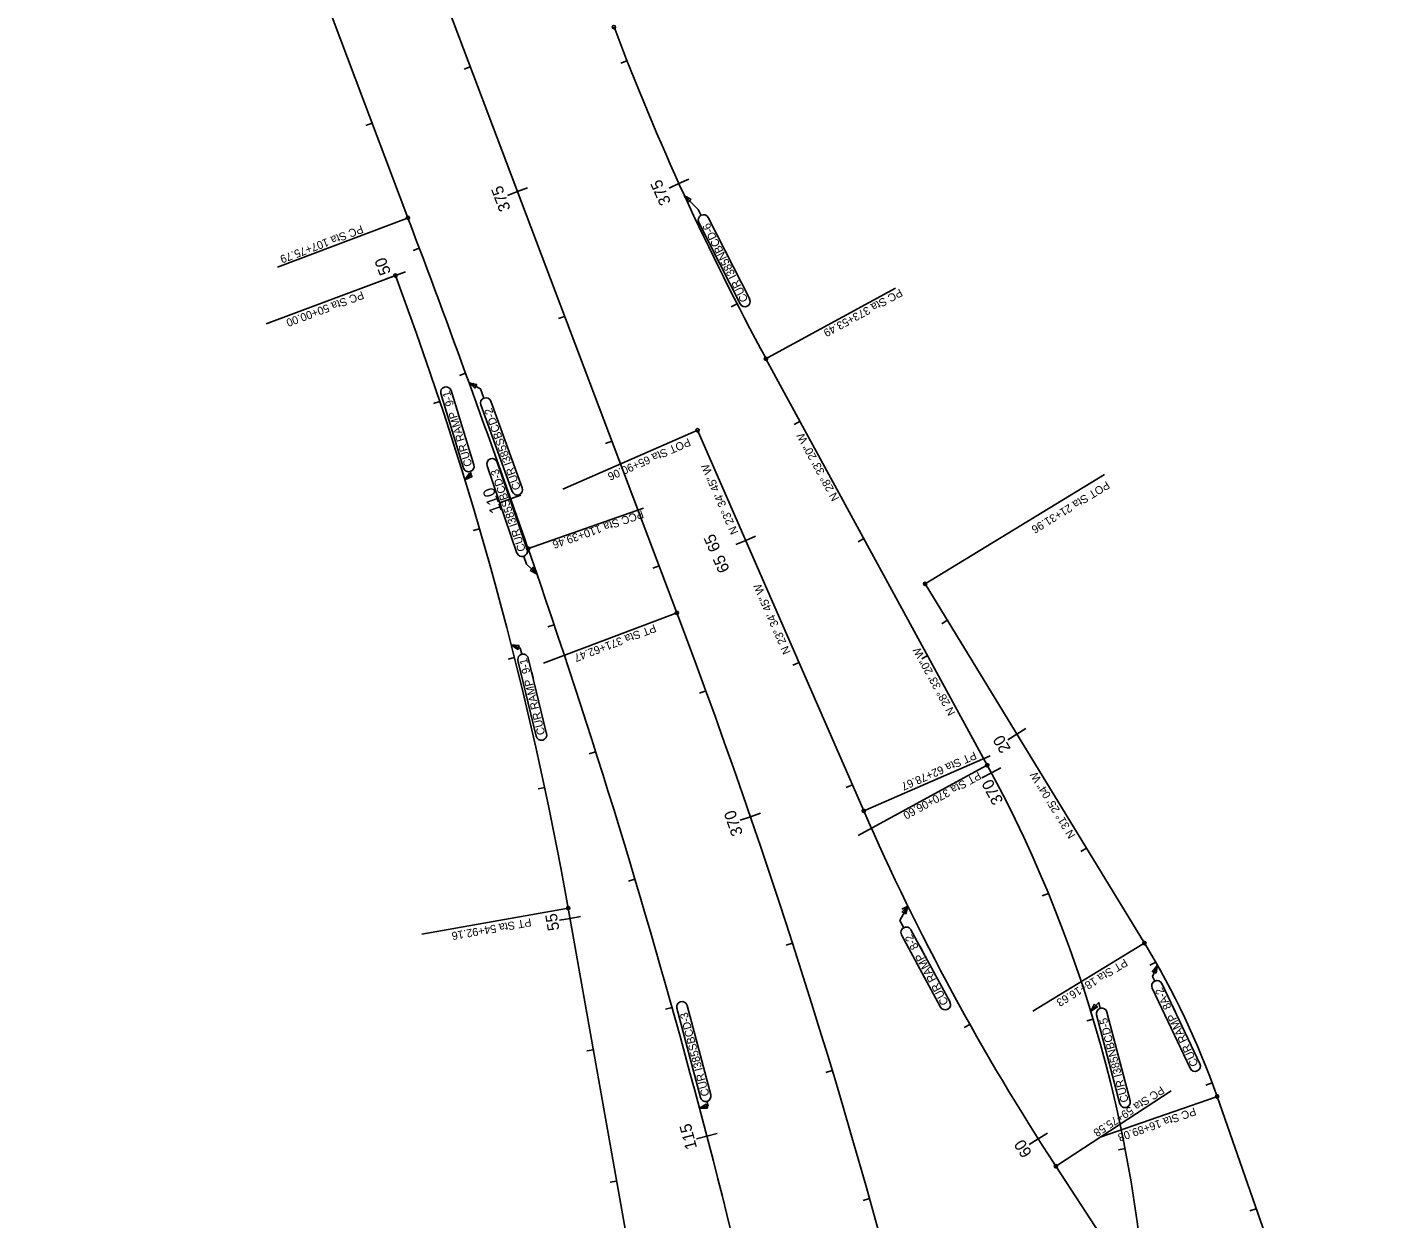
# Model space of a CAD drawing. Extents: x 1603540 to 1622629, y 1083934 to 1103503.
# Drawn here: x 1611564 to 1612578, y 1091073 to 1091966 of the extents above; entities that cross this region are included whole.
import ezdxf

# ---------------------------------------------------------------- set-up
doc = ezdxf.new("R2010")
doc.units = 0
for name, color, linetype in [('RD_EX_BldgChurch', 7, 'Continuous'), ('RD_EX_Fence_ChLk', 7, 'Continuous'), ('RD_EX_H2O', 7, 'Continuous'), ('RD_EX_Misc', 7, 'Continuous'), ('RD_HC_CL', 7, 'Continuous'), ('RD_PG_GR', 7, 'Continuous')]:
    doc.layers.add(name, color=color, linetype=linetype)

msp = doc.modelspace()

# ---------------------------------------------------------------- linework, layer by layer
at = {"layer": 'RD_EX_BldgChurch'}
for p, q in [((1611848.4, 1091822.7), (1611751.9, 1091786.2)), ((1611839, 1091779.4), (1611743.3, 1091743.7)), ((1612119, 1091718.2), (1612215, 1091770.4)), ((1612065.5, 1091663.5), (1611965.7, 1091619.9)), ((1612236.1, 1091548.1), (1612371.7, 1091630.9)), ((1611938.4, 1091574.9), (1612026.1, 1091605.5)), ((1612049.9, 1091526.7), (1611951.2, 1091489.4)), ((1612192.4, 1091379.1), (1612285.9, 1091419.9)), ((1612282.7, 1091412.3), (1612186.9, 1091360.2)), ((1611968.5, 1091305.6), (1611860.1, 1091286.3)), ((1612400.5, 1091279), (1612318, 1091228.6)), ((1612336.3, 1091113), (1612421.5, 1091168.8)), ((1612454.8, 1091164.2), (1612368.4, 1091134))]:
    msp.add_line(p, q, dxfattribs=at)
for centre in [(1612004, 1091966.2), (1611849.6, 1091823.2), (1611840.2, 1091779.9), (1612117.9, 1091717.6), (1612066.7, 1091664), (1611939.6, 1091575.3), (1612237.2, 1091548.8), (1612051.1, 1091527.2), (1612283.8, 1091412.9), (1612191.2, 1091378.6), (1611969.7, 1091305.8), (1612401.6, 1091279.6), (1612456, 1091164.6), (1612335.2, 1091112.3)]:
    msp.add_circle(centre, 1.25, dxfattribs=at)
at = {"layer": 'RD_EX_H2O'}
for p, q in [((1611896.3, 1091936.4), (1611891.6, 1091934.6)), ((1612013.7, 1091940.9), (1612009.1, 1091939)), ((1611822.8, 1091894.1), (1611818.1, 1091892.3)), ((1611931.7, 1091842.9), (1611939.1, 1091845.7)), ((1612052.7, 1091848.8), (1612045.4, 1091845.5)), ((1612052.7, 1091848.8), (1612060, 1091852.1)), ((1611931.7, 1091842.9), (1611924.2, 1091840)), ((1611858.1, 1091800.5), (1611853.4, 1091798.8)), ((1611840.2, 1091779.9), (1611832.7, 1091777.1)), ((1611840.2, 1091779.9), (1611847.7, 1091782.7)), ((1612096.2, 1091758.7), (1612091.7, 1091756.5)), ((1611967, 1091749.3), (1611962.4, 1091747.6)), ((1611892.8, 1091706.7), (1611888.1, 1091705)), ((1611873.5, 1091685.6), (1611868.7, 1091684)), ((1612143.5, 1091670.7), (1612139.1, 1091668.3)), ((1612002.4, 1091655.8), (1611997.7, 1091654)), ((1611926.5, 1091612.6), (1611919, 1091609.9)), ((1611926.5, 1091612.6), (1611934.1, 1091615.2)), ((1611903.3, 1091590.1), (1611898.5, 1091588.7)), ((1612102.7, 1091581.4), (1612095.4, 1091578.2)), ((1612102.7, 1091581.4), (1612110, 1091584.6)), ((1612191.3, 1091582.8), (1612186.9, 1091580.4)), ((1612037.8, 1091562.3), (1612033.1, 1091560.5)), ((1612253.8, 1091521.5), (1612249.6, 1091518.9)), ((1611959.2, 1091518.1), (1611954.4, 1091516.5)), ((1611929.5, 1091493.6), (1611924.6, 1091492.4)), ((1612142.7, 1091489.8), (1612138.1, 1091487.8)), ((1612239.1, 1091495), (1612234.7, 1091492.6)), ((1612072.8, 1091468.6), (1612068.1, 1091466.9)), ((1612306, 1091436.1), (1612312.8, 1091440.3)), ((1612306, 1091436.1), (1612299.1, 1091432)), ((1611990.2, 1091423), (1611985.5, 1091421.5)), ((1612286.9, 1091407.1), (1612294, 1091410.9)), ((1612182.7, 1091398.1), (1612178.1, 1091396.1)), ((1612286.9, 1091407.1), (1612279.8, 1091403.4)), ((1611952.1, 1091396.2), (1611947.2, 1091395.2)), ((1612106.2, 1091374.3), (1612098.6, 1091371.7)), ((1612106.2, 1091374.3), (1612113.8, 1091376.9)), ((1612358.1, 1091350.8), (1612353.8, 1091348.2)), ((1612019.7, 1091327.4), (1612014.9, 1091326)), ((1612329.6, 1091316.8), (1612325, 1091314.9)), ((1612224.3, 1091307.2), (1612219.8, 1091305)), ((1611971.1, 1091298.1), (1611963.2, 1091296.7)), ((1611971.1, 1091298.1), (1611979, 1091299.5)), ((1612137.8, 1091279.5), (1612133, 1091277.9)), ((1612410, 1091265.3), (1612405.7, 1091262.9)), ((1612047.5, 1091231.4), (1612042.6, 1091230)), ((1612270.7, 1091218.6), (1612266.4, 1091216.2)), ((1612363.1, 1091222.6), (1612358.4, 1091221.2)), ((1611988.6, 1091199.6), (1611983.6, 1091198.7)), ((1612167.5, 1091184), (1612162.8, 1091182.6)), ((1612452.3, 1091174.9), (1612447.6, 1091173.1)), ((1612073.6, 1091134.9), (1612065.8, 1091132.8)), ((1612073.6, 1091134.9), (1612081.3, 1091136.9)), ((1612322, 1091132.8), (1612328.8, 1091137.1)), ((1612322, 1091132.8), (1612315.3, 1091128.5)), ((1612387.1, 1091125.5), (1612382.2, 1091124.6)), ((1612006, 1091101.1), (1612001.1, 1091100.3)), ((1612195.5, 1091088), (1612190.7, 1091086.6)), ((1612485.4, 1091080.5), (1612480.6, 1091078.8))]:
    msp.add_line(p, q, dxfattribs=at)
at = {"layer": 'RD_HC_CL'}
for p, q in [((1612051.1, 1091527.2), (1611564.1, 1092814.8)), ((1611683.7, 1092261.8), (1611849.6, 1091823.2)), ((1612283.8, 1091412.9), (1612117.9, 1091717.6)), ((1612191.2, 1091378.6), (1612066.7, 1091664)), ((1612401.6, 1091279.6), (1612237.2, 1091548.8)), ((1611969.7, 1091305.8), (1612090.9, 1090622.6)), ((1612578.1, 1090814.8), (1612456, 1091164.6)), ((1612454.5, 1090930.1), (1612335.2, 1091112.3))]:
    msp.add_line(p, q, dxfattribs=at)
for centre, radius, start, end in [((1613874.7, 1092673.7), 2000, 200.7167, 208.5554), ((1602552.7, 1088307.1), 9939.5, 19.19672, 20.71665), ((1609311.2, 1090834.2), 2700, 10.058, 20.5018), ((1606462.1, 1089668.2), 5800, 10.52808, 19.19672), ((1607115.5, 1089660.5), 5276.8, 6.3858, 20.7167), ((1611405.4, 1090934.9), 1000, 0.8738, 28.5554), ((1613841, 1092098.6), 1800, 203.5791, 213.2266), ((1611889.5, 1090966.9), 600, 19.2382, 31.4178)]:
    msp.add_arc(centre, radius, start, end, dxfattribs=at)
at = {"layer": 'RD_PG_GR'}
for p, q in [((1612067.5, 1091819.6), (1612098.5, 1091758.6)), ((1612105.7, 1091762.2), (1612074.7, 1091823.3)), ((1611898.9, 1091638), (1611881.9, 1091693.7)), ((1611874.3, 1091691.4), (1611891.2, 1091635.6)), ((1611904.1, 1091683), (1611927.7, 1091618)), ((1611935.2, 1091620.7), (1611911.7, 1091685.7)), ((1611908.9, 1091637.4), (1611931.3, 1091571.9)), ((1611938.9, 1091574.5), (1611916.5, 1091640)), ((1611932, 1091491.3), (1611945.7, 1091434.6)), ((1611953.5, 1091436.5), (1611939.8, 1091493.1)), ((1612255.9, 1091235.4), (1612226.6, 1091289.5)), ((1612219.6, 1091285.7), (1612248.8, 1091231.6)), ((1612407.4, 1091245.8), (1612435.9, 1091185.7)), ((1612443.1, 1091189.1), (1612414.7, 1091249.2)), ((1612051.1, 1091230.7), (1612068.8, 1091163.8)), ((1612076.6, 1091165.8), (1612058.8, 1091232.7)), ((1612365.7, 1091225.8), (1612383.2, 1091159.2)), ((1612390.9, 1091161.3), (1612373.4, 1091227.8))]:
    msp.add_line(p, q, dxfattribs=at)
for points in [[(1612069.3, 1091825), (1612067.1, 1091829.3), (1612056.7, 1091839.9)], [(1611906.5, 1091688.1), (1611904, 1091695), (1611895.4, 1091699.6)], [(1611896.2, 1091633), (1611896.9, 1091630.8), (1611892.3, 1091626.9)], [(1611936.4, 1091569.4), (1611938.5, 1091563.5), (1611946.4, 1091556.1)], [(1611934.9, 1091496.1), (1611933.8, 1091500.7), (1611927, 1091503.2)], [(1612221.2, 1091291.1), (1612218.3, 1091296.5), (1612224.3, 1091307.2)], [(1612409.3, 1091251.1), (1612407.7, 1091254.6), (1612411.4, 1091262.9)], [(1612368.5, 1091230.7), (1612367.4, 1091235), (1612361.3, 1091228.6)], [(1612073.7, 1091160.9), (1612074.6, 1091157.7), (1612068, 1091155.9)]]:
    msp.add_lwpolyline(points, dxfattribs=at)
for points in [[(1612061.9, 1091836.9), (1612056.7, 1091839.9), (1612059.6, 1091834.7)], [(1611901.2, 1091698.2), (1611895.4, 1091699.6), (1611899.8, 1091695.5)], [(1611895.7, 1091631.8), (1611892.3, 1091626.9), (1611897.7, 1091629.4)], [(1611941.1, 1091558.9), (1611946.4, 1091556.1), (1611943.2, 1091561.2)], [(1611933, 1091502.6), (1611927, 1091503.2), (1611931.9, 1091499.7)], [(1612222.8, 1091301.4), (1612224.3, 1091307.2), (1612220.1, 1091302.9)], [(1612410.4, 1091257), (1612411.4, 1091262.9), (1612407.6, 1091258.2)], [(1612364.2, 1091233.8), (1612361.3, 1091228.6), (1612366.4, 1091231.7)], [(1612073.2, 1091158.9), (1612068, 1091155.9), (1612074, 1091155.9)]]:
    msp.add_lwpolyline(points, close=True, dxfattribs=at)
for centre, start, end in [((1612071.1, 1091821.5), 26.9145, 206.9145), ((1612102.1, 1091760.4), 206.9145, 26.9145), ((1611878.1, 1091692.5), 16.9145, 196.9145), ((1611907.9, 1091684.3), 19.9567, 199.9567), ((1611912.7, 1091638.7), 18.9145, 198.9145), ((1611895.1, 1091636.8), 196.9145, 16.9145), ((1611931.5, 1091619.4), 199.9567, 19.9567), ((1611935.1, 1091573.2), 198.9145, 18.9145), ((1611935.9, 1091492.2), 13.6561, 193.6561), ((1611949.6, 1091435.6), 193.6561, 13.6561), ((1612223.1, 1091287.6), 28.4028, 208.4028), ((1612411, 1091247.5), 25.328, 205.328), ((1612055, 1091231.7), 14.8624, 194.8624), ((1612252.3, 1091233.5), 208.4028, 28.4028), ((1612369.6, 1091226.8), 14.7146, 194.7146), ((1612439.5, 1091187.4), 205.328, 25.328), ((1612072.7, 1091164.8), 194.8624, 14.8624), ((1612387, 1091160.3), 194.7146, 14.7146)]:
    msp.add_arc(centre, 4, start, end, dxfattribs=at)

# ---------------------------------------------------------------- texts
at = {"layer": 'RD_EX_BldgChurch'}
for s, rotation, p in [('PC Sta 107+75.79', 200.7167, (1611814.7, 1091817.8)), ('PC Sta 50+00.00', 200.5018, (1611815.2, 1091768.4)), ('PC Sta 373+53.49', 208.5554, (1612218.2, 1091770.3)), ('POT Sta 65+90.06', 203.5791, (1612059.8, 1091658.2)), ('POT Sta 21+31.96', 211.4178, (1612373.2, 1091626.1)), ('PCC Sta 110+39.46', 199.1967, (1612024.9, 1091604.2)), ('PT Sta 371+62.47', 200.7167, (1612034.2, 1091518.7)), ('PT Sta 62+78.67', 203.5791, (1612274.1, 1091423.4)), ('PT Sta 370+06.60', 208.5554, (1612277.1, 1091408.3)), ('PT Sta 54+92.16', 190.058, (1611941.5, 1091298.2)), ('PT Sta 18+16.63', 211.4178, (1612386.6, 1091268.2)), ('PC Sta 59+75.58', 213.2266, (1612414, 1091172.6)), ('PC Sta 16+89.08', 199.2382, (1612439, 1091156.5))]:
    msp.add_text(s, height=6, rotation=rotation, dxfattribs=at).set_placement(p)
at = {"layer": 'RD_EX_Fence_ChLk'}
for s, rotation, p in [('N 28%%d 33\' 20" W', 118.5554, (1612172.9, 1091612.9)), ('N 23%%d 34\' 45" W', 113.5791, (1612097.3, 1091587.4)), ('N 23%%d 34\' 45" W', 113.5791, (1612136.5, 1091497.6)), ('N 28%%d 33\' 20" W', 118.5554, (1612260.1, 1091452.1)), ('N 31%%d 25\' 04" W', 121.4178, (1612350.1, 1091360.3))]:
    msp.add_text(s, height=6, rotation=rotation, dxfattribs=at).set_placement(p)
at = {"layer": 'RD_EX_Misc'}
for s, rotation, p in [('375', 110.7167, (1611926.7, 1091829.8)), ('375', 114.3583, (1612046.9, 1091834.9)), ('50', 110.5018, (1611837, 1091782.1)), ('110', 109.4242, (1611920, 1091603.4)), ('65', 113.5791, (1612084.1, 1091575.1)), ('65', 113.5791, (1612090.9, 1091559.4)), ('20', 121.4178, (1612301.7, 1091425.3)), ('370', 118.1775, (1612296.1, 1091386.1)), ('370', 108.9525, (1612100.8, 1091361.5)), ('55', 100.058, (1611963.2, 1091289.6)), ('115', 104.6472, (1612066.3, 1091126.1)), ('60', 122.4494, (1612317.7, 1091122.3))]:
    msp.add_text(s, height=8.75, rotation=rotation, dxfattribs=at).set_placement(p)
at = {"layer": 'RD_PG_GR'}
for s, rotation, p in [('CUR I385NBCD-6', 116.9145, (1612104.8, 1091761.8)), ('CUR RAMP_9-1', 106.9145, (1611897.9, 1091637.7)), ('CUR I385SBCD-2', 109.9567, (1611934.3, 1091620.4)), ('CUR I385SBCD-3', 108.9145, (1611938, 1091574.2)), ('CUR RAMP_9-1', 103.6561, (1611952.5, 1091436.3)), ('CUR RAMP_8-2', 118.4028, (1612255, 1091234.9)), ('CUR RAMP_8A-2', 115.328, (1612442.2, 1091188.7)), ('CUR I385SBCD-3', 104.8624, (1612075.6, 1091165.6)), ('CUR I385NBCD-5', 104.7146, (1612389.9, 1091161))]:
    msp.add_text(s, height=6, rotation=rotation, dxfattribs=at).set_placement(p)

doc.saveas('drawing.dxf')
